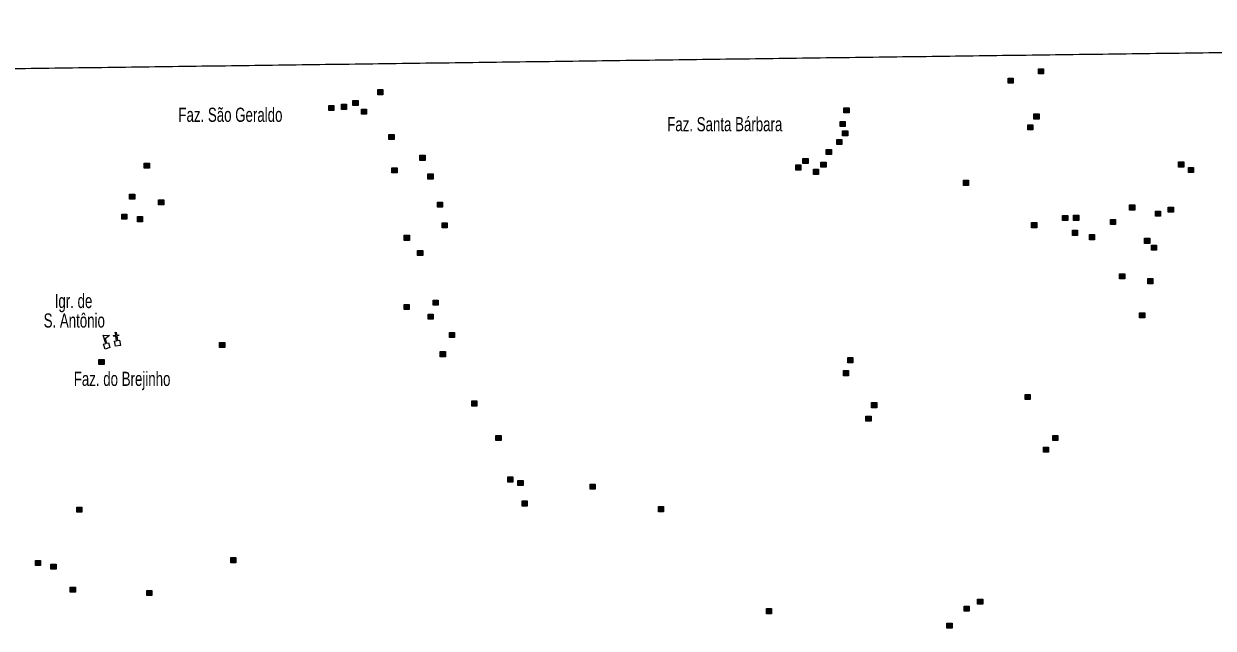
# Model space of a CAD drawing. Extents: x 265.7 to 292.1, y 7676.2 to 7704.2.
# Drawn here: x 272.32 to 279.03, y 7700.79 to 7704.2 of the extents above; entities that cross this region are included whole.
import ezdxf

# ---------------------------------------------------------------- set-up
doc = ezdxf.new("R2010")
doc.units = 0
doc.header["$LTSCALE"] = 0.032
for name, color, linetype, lineweight in [('2', 7, 'Continuous', 25), ('4', 7, 'Continuous', 25), ('6', 7, 'Continuous', 25), ('63', 7, 'Continuous', 13)]:
    doc.layers.add(name, color=color, linetype=linetype, lineweight=lineweight)
doc.layers.add('61', color=7, linetype='Continuous')

msp = doc.modelspace()

# ---------------------------------------------------------------- hatches: boundary and pattern name
at = {"layer": '2'}
for points in [[(278.0433, 7703.9493), (278.0723, 7703.9493), (278.0723, 7703.9203), (278.0433, 7703.9203)], [(277.872, 7703.897), (277.901, 7703.897), (277.901, 7703.868), (277.872, 7703.868)], [(274.3163, 7703.8315), (274.3453, 7703.8315), (274.3453, 7703.8025), (274.3163, 7703.8025)], [(274.0394, 7703.742), (274.0684, 7703.742), (274.0684, 7703.713), (274.0394, 7703.713)], [(274.1104, 7703.7492), (274.1394, 7703.7492), (274.1394, 7703.7202), (274.1104, 7703.7202)], [(274.1758, 7703.7709), (274.2048, 7703.7709), (274.2048, 7703.7419), (274.1758, 7703.7419)], [(274.2235, 7703.7219), (274.2525, 7703.7219), (274.2525, 7703.6929), (274.2235, 7703.6929)], [(276.9457, 7703.729), (276.9747, 7703.729), (276.9747, 7703.7), (276.9457, 7703.7)], [(276.9239, 7703.6523), (276.9529, 7703.6523), (276.9529, 7703.6233), (276.9239, 7703.6233)], [(278.0182, 7703.6943), (278.0472, 7703.6943), (278.0472, 7703.6653), (278.0182, 7703.6653)], [(274.3793, 7703.5781), (274.4083, 7703.5781), (274.4083, 7703.5491), (274.3793, 7703.5491)], [(276.9384, 7703.5991), (276.9674, 7703.5991), (276.9674, 7703.5701), (276.9384, 7703.5701)], [(277.9836, 7703.6332), (278.0126, 7703.6332), (278.0126, 7703.6042), (277.9836, 7703.6042)], [(276.9053, 7703.5508), (276.9343, 7703.5508), (276.9343, 7703.5218), (276.9053, 7703.5218)], [(274.5536, 7703.4611), (274.5826, 7703.4611), (274.5826, 7703.4321), (274.5536, 7703.4321)], [(276.7147, 7703.4434), (276.7437, 7703.4434), (276.7437, 7703.4144), (276.7147, 7703.4144)], [(276.8464, 7703.4942), (276.8754, 7703.4942), (276.8754, 7703.4652), (276.8464, 7703.4652)], [(272.9984, 7703.4168), (273.0274, 7703.4168), (273.0274, 7703.3878), (272.9984, 7703.3878)], [(274.3961, 7703.3908), (274.4251, 7703.3908), (274.4251, 7703.3618), (274.3961, 7703.3618)], [(276.6737, 7703.4062), (276.7027, 7703.4062), (276.7027, 7703.3772), (276.6737, 7703.3772)], [(276.7737, 7703.382), (276.8027, 7703.382), (276.8027, 7703.353), (276.7737, 7703.353)], [(276.8166, 7703.4223), (276.8456, 7703.4223), (276.8456, 7703.3933), (276.8166, 7703.3933)], [(278.8341, 7703.4232), (278.8631, 7703.4232), (278.8631, 7703.3942), (278.8341, 7703.3942)], [(278.8891, 7703.3926), (278.9181, 7703.3926), (278.9181, 7703.3636), (278.8891, 7703.3636)], [(274.5988, 7703.3555), (274.6278, 7703.3555), (274.6278, 7703.3265), (274.5988, 7703.3265)], [(277.6203, 7703.3199), (277.6493, 7703.3199), (277.6493, 7703.2909), (277.6203, 7703.2909)], [(272.9161, 7703.2416), (272.9451, 7703.2416), (272.9451, 7703.2126), (272.9161, 7703.2126)], [(273.0791, 7703.2101), (273.1081, 7703.2101), (273.1081, 7703.1811), (273.0791, 7703.1811)], [(274.6528, 7703.1973), (274.6818, 7703.1973), (274.6818, 7703.1683), (274.6528, 7703.1683)], [(278.5574, 7703.181), (278.5864, 7703.181), (278.5864, 7703.152), (278.5574, 7703.152)], [(272.8717, 7703.1294), (272.9007, 7703.1294), (272.9007, 7703.1004), (272.8717, 7703.1004)], [(272.9605, 7703.1149), (272.9895, 7703.1149), (272.9895, 7703.0859), (272.9605, 7703.0859)], [(278.1796, 7703.1214), (278.2086, 7703.1214), (278.2086, 7703.0924), (278.1796, 7703.0924)], [(278.2418, 7703.1222), (278.2708, 7703.1222), (278.2708, 7703.0932), (278.2418, 7703.0932)], [(278.7034, 7703.1456), (278.7324, 7703.1456), (278.7324, 7703.1166), (278.7034, 7703.1166)], [(278.776, 7703.1682), (278.805, 7703.1682), (278.805, 7703.1392), (278.776, 7703.1392)], [(274.6794, 7703.0803), (274.7084, 7703.0803), (274.7084, 7703.0513), (274.6794, 7703.0513)], [(278.0045, 7703.081), (278.0335, 7703.081), (278.0335, 7703.052), (278.0045, 7703.052)], [(278.4491, 7703.0987), (278.4781, 7703.0987), (278.4781, 7703.0697), (278.4491, 7703.0697)], [(274.4656, 7703.0099), (274.4946, 7703.0099), (274.4946, 7702.9809), (274.4656, 7702.9809)], [(278.2346, 7703.0381), (278.2636, 7703.0381), (278.2636, 7703.0091), (278.2346, 7703.0091)], [(278.3305, 7703.0131), (278.3595, 7703.0131), (278.3595, 7702.9841), (278.3305, 7702.9841)], [(278.6421, 7702.9931), (278.6711, 7702.9931), (278.6711, 7702.9641), (278.6421, 7702.9641)], [(274.5405, 7702.9244), (274.5695, 7702.9244), (274.5695, 7702.8954), (274.5405, 7702.8954)], [(278.6808, 7702.9544), (278.7098, 7702.9544), (278.7098, 7702.9254), (278.6808, 7702.9254)], [(278.5016, 7702.7921), (278.5306, 7702.7921), (278.5306, 7702.7631), (278.5016, 7702.7631)], [(278.6598, 7702.7655), (278.6888, 7702.7655), (278.6888, 7702.7365), (278.6598, 7702.7365)], [(274.6278, 7702.6435), (274.6568, 7702.6435), (274.6568, 7702.6145), (274.6278, 7702.6145)], [(274.4647, 7702.6194), (274.4937, 7702.6194), (274.4937, 7702.5904), (274.4647, 7702.5904)], [(278.6138, 7702.5726), (278.6428, 7702.5726), (278.6428, 7702.5436), (278.6138, 7702.5436)], [(274.5995, 7702.5645), (274.6285, 7702.5645), (274.6285, 7702.5355), (274.5995, 7702.5355)], [(274.7198, 7702.4611), (274.7488, 7702.4611), (274.7488, 7702.4321), (274.7198, 7702.4321)], [(273.4237, 7702.4046), (273.4527, 7702.4046), (273.4527, 7702.3756), (273.4237, 7702.3756)], [(272.7431, 7702.3089), (272.7721, 7702.3089), (272.7721, 7702.2799), (272.7431, 7702.2799)], [(274.6689, 7702.353), (274.6979, 7702.353), (274.6979, 7702.324), (274.6689, 7702.324)], [(276.9674, 7702.3191), (276.9964, 7702.3191), (276.9964, 7702.2901), (276.9674, 7702.2901)], [(276.9433, 7702.2458), (276.9723, 7702.2458), (276.9723, 7702.2168), (276.9433, 7702.2168)], [(277.9683, 7702.1116), (277.9973, 7702.1116), (277.9973, 7702.0826), (277.9683, 7702.0826)], [(274.8465, 7702.0747), (274.8755, 7702.0747), (274.8755, 7702.0457), (274.8465, 7702.0457)], [(277.1022, 7702.0658), (277.1312, 7702.0658), (277.1312, 7702.0368), (277.1022, 7702.0368)], [(277.0699, 7701.9891), (277.0989, 7701.9891), (277.0989, 7701.9601), (277.0699, 7701.9601)], [(274.9828, 7701.8802), (275.0118, 7701.8802), (275.0118, 7701.8512), (274.9828, 7701.8512)], [(278.1238, 7701.8801), (278.1528, 7701.8801), (278.1528, 7701.8511), (278.1238, 7701.8511)], [(278.0714, 7701.8139), (278.1004, 7701.8139), (278.1004, 7701.7849), (278.0714, 7701.7849)], [(275.0499, 7701.6461), (275.0789, 7701.6461), (275.0789, 7701.6171), (275.0499, 7701.6171)], [(275.1071, 7701.6259), (275.1361, 7701.6259), (275.1361, 7701.5969), (275.1071, 7701.5969)], [(275.514, 7701.6056), (275.543, 7701.6056), (275.543, 7701.5766), (275.514, 7701.5766)], [(275.1298, 7701.5105), (275.1588, 7701.5105), (275.1588, 7701.4815), (275.1298, 7701.4815)], [(272.6174, 7701.4758), (272.6464, 7701.4758), (272.6464, 7701.4468), (272.6174, 7701.4468)], [(275.8998, 7701.4789), (275.9288, 7701.4789), (275.9288, 7701.4499), (275.8998, 7701.4499)], [(272.385, 7701.1747), (272.414, 7701.1747), (272.414, 7701.1457), (272.385, 7701.1457)], [(273.4867, 7701.1908), (273.5157, 7701.1908), (273.5157, 7701.1618), (273.4867, 7701.1618)], [(272.4722, 7701.1538), (272.5012, 7701.1538), (272.5012, 7701.1248), (272.4722, 7701.1248)], [(272.5811, 7701.0246), (272.6101, 7701.0246), (272.6101, 7700.9956), (272.5811, 7700.9956)], [(273.0129, 7701.0053), (273.0419, 7701.0053), (273.0419, 7700.9763), (273.0129, 7700.9763)], [(276.5083, 7700.9027), (276.5373, 7700.9027), (276.5373, 7700.8737), (276.5083, 7700.8737)], [(277.6236, 7700.9173), (277.6526, 7700.9173), (277.6526, 7700.8883), (277.6236, 7700.8883)], [(277.7003, 7700.9568), (277.7293, 7700.9568), (277.7293, 7700.9278), (277.7003, 7700.9278)], [(277.5268, 7700.8213), (277.5558, 7700.8213), (277.5558, 7700.7923), (277.5268, 7700.7923)]]:
    msp.add_hatch(color=256, dxfattribs=at).paths.add_polyline_path(points)

# ---------------------------------------------------------------- linework, layer by layer
for points in [[(278.0433, 7703.9493), (278.0723, 7703.9493), (278.0723, 7703.9203), (278.0433, 7703.9203)], [(277.872, 7703.897), (277.901, 7703.897), (277.901, 7703.868), (277.872, 7703.868)], [(274.3163, 7703.8315), (274.3453, 7703.8315), (274.3453, 7703.8025), (274.3163, 7703.8025)], [(274.0394, 7703.742), (274.0684, 7703.742), (274.0684, 7703.713), (274.0394, 7703.713)], [(274.1104, 7703.7492), (274.1394, 7703.7492), (274.1394, 7703.7202), (274.1104, 7703.7202)], [(274.1758, 7703.7709), (274.2048, 7703.7709), (274.2048, 7703.7419), (274.1758, 7703.7419)], [(274.2235, 7703.7219), (274.2525, 7703.7219), (274.2525, 7703.6929), (274.2235, 7703.6929)], [(276.9457, 7703.729), (276.9747, 7703.729), (276.9747, 7703.7), (276.9457, 7703.7)], [(276.9239, 7703.6523), (276.9529, 7703.6523), (276.9529, 7703.6233), (276.9239, 7703.6233)], [(278.0182, 7703.6943), (278.0472, 7703.6943), (278.0472, 7703.6653), (278.0182, 7703.6653)], [(274.3793, 7703.5781), (274.4083, 7703.5781), (274.4083, 7703.5491), (274.3793, 7703.5491)], [(276.9384, 7703.5991), (276.9674, 7703.5991), (276.9674, 7703.5701), (276.9384, 7703.5701)], [(277.9836, 7703.6332), (278.0126, 7703.6332), (278.0126, 7703.6042), (277.9836, 7703.6042)], [(276.9053, 7703.5508), (276.9343, 7703.5508), (276.9343, 7703.5218), (276.9053, 7703.5218)], [(274.5536, 7703.4611), (274.5826, 7703.4611), (274.5826, 7703.4321), (274.5536, 7703.4321)], [(276.7147, 7703.4434), (276.7437, 7703.4434), (276.7437, 7703.4144), (276.7147, 7703.4144)], [(276.8464, 7703.4942), (276.8754, 7703.4942), (276.8754, 7703.4652), (276.8464, 7703.4652)], [(272.9984, 7703.4168), (273.0274, 7703.4168), (273.0274, 7703.3878), (272.9984, 7703.3878)], [(274.3961, 7703.3908), (274.4251, 7703.3908), (274.4251, 7703.3618), (274.3961, 7703.3618)], [(276.6737, 7703.4062), (276.7027, 7703.4062), (276.7027, 7703.3772), (276.6737, 7703.3772)], [(276.7737, 7703.382), (276.8027, 7703.382), (276.8027, 7703.353), (276.7737, 7703.353)], [(276.8166, 7703.4223), (276.8456, 7703.4223), (276.8456, 7703.3933), (276.8166, 7703.3933)], [(278.8341, 7703.4232), (278.8631, 7703.4232), (278.8631, 7703.3942), (278.8341, 7703.3942)], [(278.8891, 7703.3926), (278.9181, 7703.3926), (278.9181, 7703.3636), (278.8891, 7703.3636)], [(274.5988, 7703.3555), (274.6278, 7703.3555), (274.6278, 7703.3265), (274.5988, 7703.3265)], [(277.6203, 7703.3199), (277.6493, 7703.3199), (277.6493, 7703.2909), (277.6203, 7703.2909)], [(272.9161, 7703.2416), (272.9451, 7703.2416), (272.9451, 7703.2126), (272.9161, 7703.2126)], [(273.0791, 7703.2101), (273.1081, 7703.2101), (273.1081, 7703.1811), (273.0791, 7703.1811)], [(274.6528, 7703.1973), (274.6818, 7703.1973), (274.6818, 7703.1683), (274.6528, 7703.1683)], [(278.5574, 7703.181), (278.5864, 7703.181), (278.5864, 7703.152), (278.5574, 7703.152)], [(272.8717, 7703.1294), (272.9007, 7703.1294), (272.9007, 7703.1004), (272.8717, 7703.1004)], [(272.9605, 7703.1149), (272.9895, 7703.1149), (272.9895, 7703.0859), (272.9605, 7703.0859)], [(278.1796, 7703.1214), (278.2086, 7703.1214), (278.2086, 7703.0924), (278.1796, 7703.0924)], [(278.2418, 7703.1222), (278.2708, 7703.1222), (278.2708, 7703.0932), (278.2418, 7703.0932)], [(278.7034, 7703.1456), (278.7324, 7703.1456), (278.7324, 7703.1166), (278.7034, 7703.1166)], [(278.776, 7703.1682), (278.805, 7703.1682), (278.805, 7703.1392), (278.776, 7703.1392)], [(274.6794, 7703.0803), (274.7084, 7703.0803), (274.7084, 7703.0513), (274.6794, 7703.0513)], [(278.0045, 7703.081), (278.0335, 7703.081), (278.0335, 7703.052), (278.0045, 7703.052)], [(278.4491, 7703.0987), (278.4781, 7703.0987), (278.4781, 7703.0697), (278.4491, 7703.0697)], [(274.4656, 7703.0099), (274.4946, 7703.0099), (274.4946, 7702.9809), (274.4656, 7702.9809)], [(278.2346, 7703.0381), (278.2636, 7703.0381), (278.2636, 7703.0091), (278.2346, 7703.0091)], [(278.3305, 7703.0131), (278.3595, 7703.0131), (278.3595, 7702.9841), (278.3305, 7702.9841)], [(278.6421, 7702.9931), (278.6711, 7702.9931), (278.6711, 7702.9641), (278.6421, 7702.9641)], [(274.5405, 7702.9244), (274.5695, 7702.9244), (274.5695, 7702.8954), (274.5405, 7702.8954)], [(278.6808, 7702.9544), (278.7098, 7702.9544), (278.7098, 7702.9254), (278.6808, 7702.9254)], [(278.5016, 7702.7921), (278.5306, 7702.7921), (278.5306, 7702.7631), (278.5016, 7702.7631)], [(278.6598, 7702.7655), (278.6888, 7702.7655), (278.6888, 7702.7365), (278.6598, 7702.7365)], [(274.6278, 7702.6435), (274.6568, 7702.6435), (274.6568, 7702.6145), (274.6278, 7702.6145)], [(274.4647, 7702.6194), (274.4937, 7702.6194), (274.4937, 7702.5904), (274.4647, 7702.5904)], [(278.6138, 7702.5726), (278.6428, 7702.5726), (278.6428, 7702.5436), (278.6138, 7702.5436)], [(274.5995, 7702.5645), (274.6285, 7702.5645), (274.6285, 7702.5355), (274.5995, 7702.5355)], [(274.7198, 7702.4611), (274.7488, 7702.4611), (274.7488, 7702.4321), (274.7198, 7702.4321)], [(273.4237, 7702.4046), (273.4527, 7702.4046), (273.4527, 7702.3756), (273.4237, 7702.3756)], [(272.7431, 7702.3089), (272.7721, 7702.3089), (272.7721, 7702.2799), (272.7431, 7702.2799)], [(274.6689, 7702.353), (274.6979, 7702.353), (274.6979, 7702.324), (274.6689, 7702.324)], [(276.9674, 7702.3191), (276.9964, 7702.3191), (276.9964, 7702.2901), (276.9674, 7702.2901)], [(276.9433, 7702.2458), (276.9723, 7702.2458), (276.9723, 7702.2168), (276.9433, 7702.2168)], [(277.9683, 7702.1116), (277.9973, 7702.1116), (277.9973, 7702.0826), (277.9683, 7702.0826)], [(274.8465, 7702.0747), (274.8755, 7702.0747), (274.8755, 7702.0457), (274.8465, 7702.0457)], [(277.1022, 7702.0658), (277.1312, 7702.0658), (277.1312, 7702.0368), (277.1022, 7702.0368)], [(277.0699, 7701.9891), (277.0989, 7701.9891), (277.0989, 7701.9601), (277.0699, 7701.9601)], [(274.9828, 7701.8802), (275.0118, 7701.8802), (275.0118, 7701.8512), (274.9828, 7701.8512)], [(278.1238, 7701.8801), (278.1528, 7701.8801), (278.1528, 7701.8511), (278.1238, 7701.8511)], [(278.0714, 7701.8139), (278.1004, 7701.8139), (278.1004, 7701.7849), (278.0714, 7701.7849)], [(275.0499, 7701.6461), (275.0789, 7701.6461), (275.0789, 7701.6171), (275.0499, 7701.6171)], [(275.1071, 7701.6259), (275.1361, 7701.6259), (275.1361, 7701.5969), (275.1071, 7701.5969)], [(275.514, 7701.6056), (275.543, 7701.6056), (275.543, 7701.5766), (275.514, 7701.5766)], [(275.1298, 7701.5105), (275.1588, 7701.5105), (275.1588, 7701.4815), (275.1298, 7701.4815)], [(272.6174, 7701.4758), (272.6464, 7701.4758), (272.6464, 7701.4468), (272.6174, 7701.4468)], [(275.8998, 7701.4789), (275.9288, 7701.4789), (275.9288, 7701.4499), (275.8998, 7701.4499)], [(272.385, 7701.1747), (272.414, 7701.1747), (272.414, 7701.1457), (272.385, 7701.1457)], [(273.4867, 7701.1908), (273.5157, 7701.1908), (273.5157, 7701.1618), (273.4867, 7701.1618)], [(272.4722, 7701.1538), (272.5012, 7701.1538), (272.5012, 7701.1248), (272.4722, 7701.1248)], [(272.5811, 7701.0246), (272.6101, 7701.0246), (272.6101, 7700.9956), (272.5811, 7700.9956)], [(273.0129, 7701.0053), (273.0419, 7701.0053), (273.0419, 7700.9763), (273.0129, 7700.9763)], [(276.5083, 7700.9027), (276.5373, 7700.9027), (276.5373, 7700.8737), (276.5083, 7700.8737)], [(277.6236, 7700.9173), (277.6526, 7700.9173), (277.6526, 7700.8883), (277.6236, 7700.8883)], [(277.7003, 7700.9568), (277.7293, 7700.9568), (277.7293, 7700.9278), (277.7003, 7700.9278)], [(277.5268, 7700.8213), (277.5558, 7700.8213), (277.5558, 7700.7923), (277.5268, 7700.7923)]]:
    msp.add_lwpolyline(points, close=True, dxfattribs=at)
at = {"layer": '4'}
for points in [[(272.7808, 7702.3986), (272.7674, 7702.4452), (272.8032, 7702.4434), (272.7783, 7702.4251), (272.7855, 7702.4)], [(272.7855, 7702.4), (272.7971, 7702.4033), (272.8051, 7702.3755), (272.7772, 7702.3675), (272.7692, 7702.3953), (272.7808, 7702.3986)]]:
    msp.add_lwpolyline(points, dxfattribs=at)
at = {"layer": '6'}
for points in [[(272.8428, 7702.4141), (272.8382, 7702.4408), (272.8263, 7702.4388), (272.8255, 7702.4436), (272.8374, 7702.4456), (272.8347, 7702.4618), (272.8394, 7702.4626), (272.8421, 7702.4464), (272.8541, 7702.4484), (272.8549, 7702.4436), (272.843, 7702.4416), (272.8475, 7702.4149)], [(272.8475, 7702.4149), (272.8594, 7702.4169), (272.8643, 7702.3883), (272.8357, 7702.3834), (272.8308, 7702.412), (272.8428, 7702.4141)]]:
    msp.add_lwpolyline(points, dxfattribs=at)
at = {"layer": '63'}
msp.add_spline([(265.7179, 7703.8606), (266.2494, 7703.868), (266.7808, 7703.8754), (267.3123, 7703.8828), (267.8437, 7703.8901), (268.3752, 7703.8974), (268.9066, 7703.9047), (269.4381, 7703.912), (269.9695, 7703.9193), (270.501, 7703.9265), (271.0324, 7703.9338), (271.5639, 7703.941), (272.0953, 7703.9482), (272.6268, 7703.9554), (273.1582, 7703.9626), (273.6896, 7703.9697), (274.2211, 7703.9769), (274.7525, 7703.984), (275.2839, 7703.9911), (275.8154, 7703.9982), (276.3468, 7704.0052), (276.8782, 7704.0123), (277.4097, 7704.0193), (277.9411, 7704.0263), (278.4725, 7704.0333), (279.0039, 7704.0403), (279.5354, 7704.0473), (280.0668, 7704.0543), (280.5982, 7704.0612), (281.1296, 7704.0681), (281.661, 7704.075), (282.1925, 7704.0819), (282.7239, 7704.0888), (283.2553, 7704.0956), (283.7867, 7704.1025), (284.3181, 7704.1093), (284.8495, 7704.1161), (285.3809, 7704.1229), (285.9123, 7704.1296), (286.4437, 7704.1364), (286.9751, 7704.1431), (287.5065, 7704.1498), (288.0379, 7704.1565), (288.5693, 7704.1632), (289.1007, 7704.1699), (289.6321, 7704.1765), (290.1635, 7704.1832), (290.6949, 7704.1898), (291.2263, 7704.1964), (291.7577, 7704.203)], degree=3, dxfattribs=at)

# ---------------------------------------------------------------- texts
at = {"layer": '61', "width": 0.7}
for s, p in [('Faz. São Geraldo', (273.1912, 7703.6496)), ('Faz. Santa Bárbara', (275.949, 7703.5965)), ('   Igr. de', (272.4309, 7702.599)), ('S. Antônio', (272.4309, 7702.489)), ('Faz. do Brejinho', (272.6008, 7702.1594))]:
    msp.add_text(s, height=0.08, dxfattribs=at).set_placement(p)

doc.saveas('drawing.dxf')
